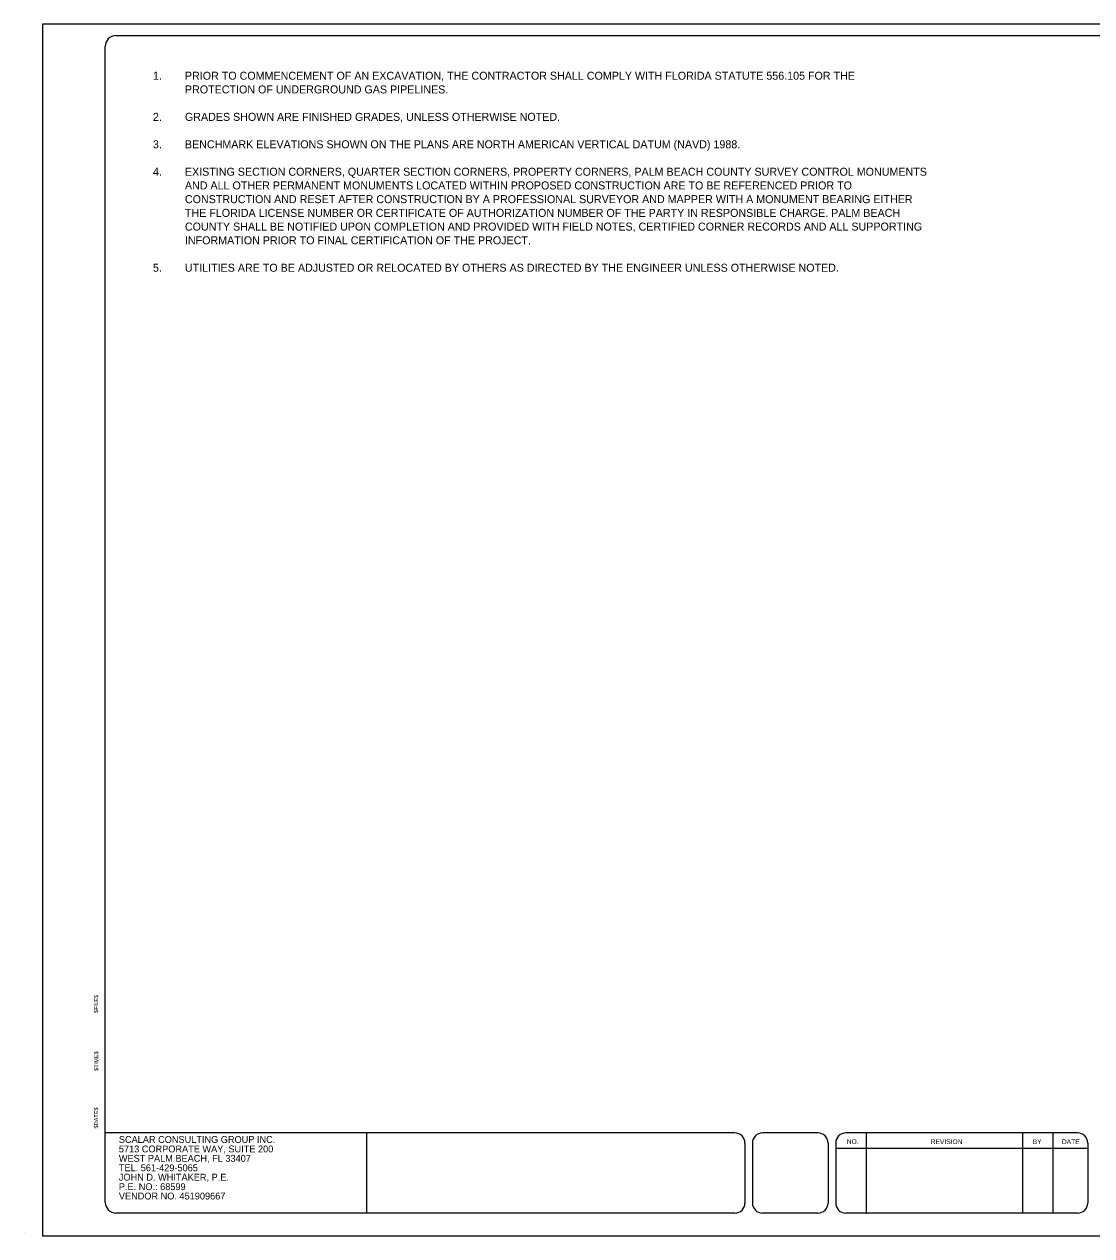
# Model space of a CAD drawing. Extents: x 783907 to 784590, y 832093 to 832609.
# Drawn here: x 784222.4 to 784315.7, y 832093.3 to 832199.3 of the extents above; entities that cross this region are included whole.
import ezdxf

# ---------------------------------------------------------------- set-up
doc = ezdxf.new("R2010")
doc.units = 0
for name, color, linetype in [('AdhocPoint_dp', 7, 'Continuous'), ('Default', 7, 'Continuous'), ('PlotBorder_dp', 7, 'Continuous'), ('TextLabel', 7, 'Continuous')]:
    doc.layers.add(name, color=color, linetype=linetype)

msp = doc.modelspace()

# ---------------------------------------------------------------- linework, layer by layer
at = {"layer": 'AdhocPoint_dp'}
msp.add_line((784222.35, 832093.55), (784222.35, 832093.55), dxfattribs=at)
at = {"layer": 'Default'}
for p, q in [((784382.69, 832198.25), (784230.37, 832198.25)), ((784229.44, 832096.18), (784229.44, 832197.32)), ((784284.52, 832102.25), (784229.44, 832102.25)), ((784252.33, 832095.24), (784252.33, 832102.25)), ((784291.79, 832102.25), (784286.94, 832102.25)), ((784314.51, 832102.25), (784294.22, 832102.25)), ((784296.02, 832102.22), (784296.02, 832095.16)), ((784309.69, 832102.22), (784309.69, 832095.25)), ((784312.34, 832102.22), (784312.34, 832095.25)), ((784285.4, 832101.37), (784285.4, 832096.12)), ((784286.06, 832101.37), (784286.06, 832096.12)), ((784292.68, 832101.37), (784292.68, 832096.12)), ((784293.34, 832101.37), (784293.34, 832096.12)), ((784315.39, 832101.37), (784315.39, 832096.12)), ((784315.43, 832100.9), (784293.37, 832100.9)), ((784284.52, 832095.24), (784230.37, 832095.24)), ((784291.79, 832095.24), (784286.94, 832095.24)), ((784314.51, 832095.24), (784294.22, 832095.24))]:
    msp.add_line(p, q, dxfattribs=at)
for centre, major_axis, start_param, end_param in [((784230.37, 832197.32), (0, -0.935), 3.141593, 4.712389), ((784284.52, 832101.37), (0, 0.882), 4.712389, 6.283185), ((784286.94, 832101.37), (0, 0.882), 0, 1.570796), ((784291.79, 832101.37), (0, 0.882), 4.712389, 6.283185), ((784294.22, 832101.37), (0, 0.882), 0, 1.570796), ((784314.51, 832101.37), (0, 0.882), 4.712389, 6.283185), ((784230.37, 832096.18), (0, -0.935), 4.712389, 6.283185), ((784284.52, 832096.12), (0, 0.882), 3.141593, 4.712389), ((784286.94, 832096.12), (0, -0.882), 4.712389, 6.283185), ((784291.79, 832096.12), (0, 0.882), 3.141593, 4.712389), ((784294.22, 832096.12), (0, -0.882), 4.712389, 6.283185), ((784314.51, 832096.12), (0, 0.882), 3.141593, 4.712389)]:
    msp.add_ellipse(centre, major_axis=major_axis, ratio=0.999927, start_param=start_param, end_param=end_param, dxfattribs=at)
at = {"layer": 'PlotBorder_dp'}
msp.add_lwpolyline([(784223.94, 832093.25), (784388.94, 832093.25), (784388.94, 832199.25), (784223.94, 832199.25)], close=True, dxfattribs=at)

# ---------------------------------------------------------------- texts
at = {"layer": 'Default'}
for s, p in [('$FILE$', (784228.82, 832112.76)), ('$TIME$', (784228.83, 832107.69)), ('$DATE$', (784228.82, 832102.64))]:
    msp.add_text(s, height=0.354, rotation=90, dxfattribs=at).set_placement(p)
for s, height, p in [('SCALAR CONSULTING GROUP INC.', 0.6, (784230.63, 832101.38)), ('5713 CORPORATE WAY, SUITE 200', 0.6, (784230.63, 832100.55)), ('NO.', 0.421, (784294.31, 832101.28)), ('REVISION', 0.421, (784301.65, 832101.28)), ('BY', 0.421, (784310.58, 832101.28)), ('DATE', 0.421, (784313.13, 832101.27)), ('WEST PALM BEACH, FL 33407', 0.6, (784230.63, 832099.73)), ('TEL. 561-429-5065', 0.6, (784230.63, 832098.9)), ('JOHN D. WHITAKER, P.E.', 0.6, (784230.63, 832098.08)), ('VENDOR NO. 451909667', 0.6, (784230.63, 832096.43)), ('P.E. NO.: 68599', 0.6, (784230.63, 832097.25))]:
    msp.add_text(s, height=height, dxfattribs=at).set_placement(p)
at = {"layer": 'TextLabel'}
for s, p in [('1.', (784233.61, 832194.4)), ('PRIOR TO COMMENCEMENT OF AN EXCAVATION, THE CONTRACTOR SHALL COMPLY WITH FLORIDA STATUTE 556.105 FOR THE', (784236.41, 832194.4)), ('PROTECTION OF UNDERGROUND GAS PIPELINES.', (784236.41, 832193.2)), ('2.', (784233.61, 832190.8)), ('GRADES SHOWN ARE FINISHED GRADES, UNLESS OTHERWISE NOTED.', (784236.41, 832190.8)), ('3.', (784233.61, 832188.4)), ('BENCHMARK ELEVATIONS SHOWN ON THE PLANS ARE NORTH AMERICAN VERTICAL DATUM (NAVD) 1988.', (784236.41, 832188.4)), ('4.', (784233.61, 832186)), ('EXISTING SECTION CORNERS, QUARTER SECTION CORNERS, PROPERTY CORNERS, PALM BEACH COUNTY SURVEY CONTROL MONUMENTS ', (784236.41, 832186)), ('AND ALL OTHER PERMANENT MONUMENTS LOCATED WITHIN PROPOSED CONSTRUCTION ARE TO BE REFERENCED PRIOR TO', (784236.41, 832184.8)), ('CONSTRUCTION AND RESET AFTER CONSTRUCTION BY A PROFESSIONAL SURVEYOR AND MAPPER WITH A MONUMENT BEARING EITHER', (784236.41, 832183.6)), ('THE FLORIDA LICENSE NUMBER OR CERTIFICATE OF AUTHORIZATION NUMBER OF THE PARTY IN RESPONSIBLE CHARGE. PALM BEACH ', (784236.41, 832182.4)), ('COUNTY SHALL BE NOTIFIED UPON COMPLETION AND PROVIDED WITH FIELD NOTES, CERTIFIED CORNER RECORDS AND ALL SUPPORTING', (784236.41, 832181.2)), ('INFORMATION PRIOR TO FINAL CERTIFICATION OF THE PROJECT.', (784236.41, 832180)), ('5.', (784233.61, 832177.6)), ('UTILITIES ARE TO BE ADJUSTED OR RELOCATED BY OTHERS AS DIRECTED BY THE ENGINEER UNLESS OTHERWISE NOTED.', (784236.41, 832177.6))]:
    msp.add_text(s, height=0.7, dxfattribs=at).set_placement(p)

doc.saveas('drawing.dxf')
